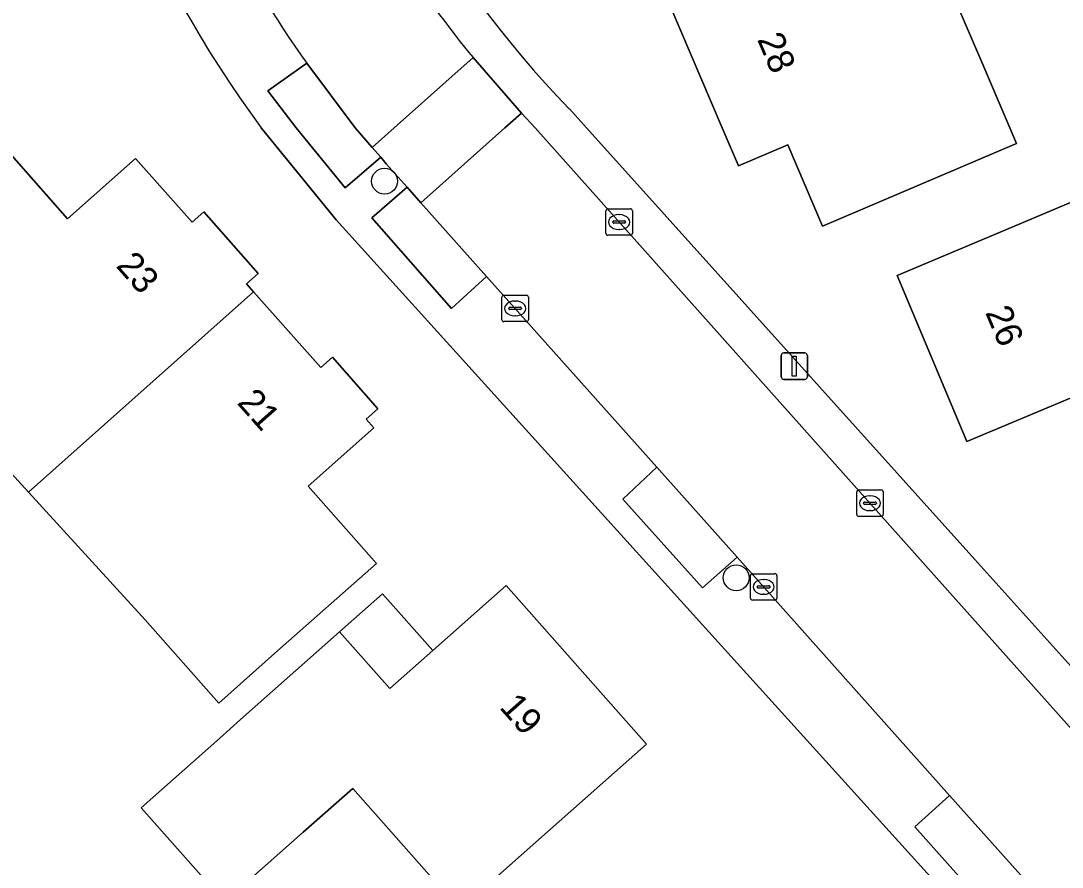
# Model space of a CAD drawing. Extents: x 158472 to 159562, y 388525 to 389606.
# Drawn here: x 158562.75 to 158602.12, y 388972.05 to 389004.05 of the extents above; entities that cross this region are included whole.
import ezdxf

# ---------------------------------------------------------------- set-up
doc = ezdxf.new("R2010")
doc.units = 0
for name, color, linetype in [('IMGEO_Boom', 7, 'Continuous'), ('IMGEO_Erf', 7, 'Continuous'), ('IMGEO_Kolk', 7, 'Continuous'), ('IMGEO_Lichtmast', 7, 'Continuous'), ('IMGEO_Pand', 7, 'Continuous'), ('IMGEO_Pand_nummerreeks', 7, 'Continuous'), ('IMGEO_Pand_overbouw', 7, 'Continuous'), ('IMGEO_Parkeervlak_open', 7, 'Continuous'), ('IMGEO_Rijbaan_lokaal_open', 7, 'Continuous'), ('IMGEO_Voetpad_open', 7, 'Continuous')]:
    doc.layers.add(name, color=color, linetype=linetype)

msp = doc.modelspace()

# ---------------------------------------------------------------- linework, layer by layer
at = {"layer": 'IMGEO_Boom'}
for centre in [(158576.499, 388997.986), (158589.795, 388982.99)]:
    msp.add_circle(centre, 0.489, dxfattribs=at)
at = {"layer": 'IMGEO_Erf'}
for points in [[(158602.302, 389007.333), (158597.826, 389005.427), (158599.08, 389002.483), (158600.39, 388999.407), (158593.063, 388996.286), (158591.753, 388999.362), (158589.877, 388998.563), (158589.266, 389000), (158587.286, 389004.646), (158590.327, 389005.942), (158588.597, 389010.003), (158593.198, 389011.963), (158599.235, 389014.534)], [(158570.23, 388978.252), (158567.451, 388981.394), (158563.036, 388986.227), (158560.673, 388988.814), (158560.23, 388988.409), (158553.333, 388986.547), (158550.683, 388989.543), (158558.185, 388996.179), (158561.93, 388999.491), (158564.515, 388996.568), (158567.089, 388998.844), (158569.222, 388996.432), (158569.665, 388996.824), (158571.726, 388994.495), (158571.282, 388994.102), (158571.547, 388993.803), (158574.084, 388990.935), (158574.526, 388991.326), (158576.249, 388989.379), (158575.806, 388988.987), (158576.098, 388988.658), (158573.613, 388986.459), (158576.201, 388983.533), (158572.456, 388980.221)], [(158606.765, 388994.404), (158608.141, 388994.982), (158609.038, 388992.848), (158610.51, 388989.345), (158608.463, 388988.485), (158603.853, 388986.547), (158602.481, 388989.812), (158598.518, 388988.146), (158595.878, 388994.425), (158600.488, 388996.363), (158605.122, 388998.311)], [(158579.346, 388970.448), (158575.294, 388975.023), (158573.422, 388973.365), (158570.449, 388970.732), (158567.294, 388974.295), (158570.267, 388976.928), (158571.057, 388977.628), (158574.8, 388980.942), (158576.426, 388982.381), (158578.325, 388980.237), (158581.102, 388982.696), (158586.409, 388976.703), (158582.666, 388973.389)], [(158574.8, 388980.942), (158576.7, 388978.797), (158578.325, 388980.237), (158576.426, 388982.381)]]:
    msp.add_lwpolyline(points, close=True, dxfattribs=at)
for points in [[(158583.486, 389000.717), (158584.132, 389000), (158598.813, 388983.685), (158608.009, 388973.467)], [(158631.972, 388946.242), (158635.311, 388942.532), (158643.817, 388950.009), (158644.553, 388955.191), (158638.495, 388969.468), (158636.325, 388970.661), (158633.535, 388969.353), (158634.702, 388966.578), (158636.899, 388967.502), (158642.704, 388953.698), (158640.483, 388952.764), (158640.89, 388951.797), (158637.438, 388950.345), (158637.031, 388951.312), (158630.51, 388948.57), (158623.539, 388965.148), (158608.557, 388958.887), (158601.535, 388966.825), (158598.936, 388969.698), (158591.991, 388977.375), (158574.672, 388996.519), (158571.833, 389000)]]:
    msp.add_lwpolyline(points, dxfattribs=at)
for centre, radius, start, end in [((158607.781, 389026.445), 44.627, 187.8492, 216.3397), ((158612.509, 389028.748), 40.35, 193.9452, 224.0034)]:
    msp.add_arc(centre, radius, start, end, dxfattribs=at)
at = {"layer": 'IMGEO_Kolk'}
for p, q in [((158584.869, 388996.014), (158584.869, 388996.866)), ((158584.944, 388996.94), (158585.796, 388996.94)), ((158585.357, 388996.72), (158585.382, 388996.72)), ((158585.87, 388996.866), (158585.87, 388996.014)), ((158585.128, 388996.434), (158585.128, 388996.446)), ((158585.566, 388996.397), (158585.168, 388996.397)), ((158585.171, 388996.483), (158585.569, 388996.483)), ((158585.612, 388996.446), (158585.612, 388996.434)), ((158585.796, 388995.94), (158584.944, 388995.94)), ((158585.38, 388996.16), (158585.355, 388996.16)), ((158580.939, 388992.748), (158580.939, 388993.6)), ((158581.014, 388993.674), (158581.866, 388993.674)), ((158581.94, 388993.6), (158581.94, 388992.748)), ((158581.198, 388993.168), (158581.198, 388993.18)), ((158581.636, 388993.131), (158581.238, 388993.131)), ((158581.241, 388993.217), (158581.639, 388993.217)), ((158581.427, 388993.454), (158581.452, 388993.454)), ((158581.682, 388993.18), (158581.682, 388993.168)), ((158581.45, 388992.894), (158581.425, 388992.894)), ((158581.866, 388992.674), (158581.014, 388992.674)), ((158594.353, 388985.383), (158594.353, 388986.235)), ((158594.428, 388986.309), (158595.28, 388986.309)), ((158594.841, 388986.089), (158594.866, 388986.089)), ((158595.354, 388986.235), (158595.354, 388985.383)), ((158594.612, 388985.803), (158594.612, 388985.815)), ((158595.05, 388985.766), (158594.652, 388985.766)), ((158594.655, 388985.852), (158595.053, 388985.852)), ((158595.096, 388985.815), (158595.096, 388985.803)), ((158595.28, 388985.309), (158594.428, 388985.309)), ((158594.864, 388985.529), (158594.839, 388985.529)), ((158590.333, 388982.219), (158590.333, 388983.071)), ((158590.408, 388983.145), (158591.26, 388983.145)), ((158590.821, 388982.925), (158590.846, 388982.925)), ((158591.334, 388983.071), (158591.334, 388982.219)), ((158590.592, 388982.639), (158590.592, 388982.651)), ((158591.03, 388982.602), (158590.632, 388982.602)), ((158590.635, 388982.688), (158591.033, 388982.688)), ((158591.076, 388982.651), (158591.076, 388982.639)), ((158591.26, 388982.145), (158590.408, 388982.145)), ((158590.844, 388982.365), (158590.819, 388982.365))]:
    msp.add_line(p, q, dxfattribs=at)
for points in [[(158584.869, 388996.014), (158584.869, 388996.866)], [(158584.944, 388996.94), (158585.796, 388996.94)], [(158585.87, 388996.866), (158585.87, 388996.014)], [(158585.796, 388995.94), (158584.944, 388995.94)], [(158580.939, 388992.748), (158580.939, 388993.6)], [(158581.014, 388993.674), (158581.866, 388993.674)], [(158581.94, 388993.6), (158581.94, 388992.748)], [(158581.866, 388992.674), (158581.014, 388992.674)], [(158594.353, 388985.383), (158594.353, 388986.235)], [(158594.428, 388986.309), (158595.28, 388986.309)], [(158595.354, 388986.235), (158595.354, 388985.383)], [(158595.28, 388985.309), (158594.428, 388985.309)], [(158590.333, 388982.219), (158590.333, 388983.071)], [(158590.408, 388983.145), (158591.26, 388983.145)], [(158591.334, 388983.071), (158591.334, 388982.219)], [(158591.26, 388982.145), (158590.408, 388982.145)]]:
    msp.add_lwpolyline(points, dxfattribs=at)
for centre, radius, start, end in [((158584.946, 388996.864), 0.0765, 91.552, 178.448), ((158584.946, 388996.864), 0.0765, 91.552, 178.448), ((158585.794, 388996.864), 0.0765, 1.552, 88.448), ((158585.794, 388996.864), 0.0765, 1.552, 88.448), ((158585.168, 388996.443), 0.0403, 85.8775, 175.7526), ((158585.165, 388996.433), 0.0366, 178.938, 274.7102), ((158585.569, 388996.44), 0.043, 264.8664, 352.4533), ((158585.573, 388996.445), 0.0386, 1.7309, 96.639), ((158584.946, 388996.016), 0.0765, 181.552, 268.448), ((158584.946, 388996.016), 0.0765, 181.552, 268.448), ((158585.794, 388996.016), 0.0765, 271.552, 358.448), ((158585.794, 388996.016), 0.0765, 271.552, 358.448), ((158581.016, 388993.598), 0.0765, 91.552, 178.448), ((158581.016, 388993.598), 0.0765, 91.552, 178.448), ((158581.864, 388993.598), 0.0765, 1.552, 88.448), ((158581.864, 388993.598), 0.0765, 1.552, 88.448), ((158581.238, 388993.177), 0.0403, 85.8775, 175.7526), ((158581.235, 388993.167), 0.0366, 178.938, 274.7102), ((158581.639, 388993.174), 0.043, 264.8664, 352.4533), ((158581.643, 388993.179), 0.0386, 1.7309, 96.639), ((158581.016, 388992.75), 0.0765, 181.552, 268.448), ((158581.016, 388992.75), 0.0765, 181.552, 268.448), ((158581.864, 388992.75), 0.0765, 271.552, 358.448), ((158581.864, 388992.75), 0.0765, 271.552, 358.448), ((158594.43, 388986.233), 0.0765, 91.552, 178.448), ((158594.43, 388986.233), 0.0765, 91.552, 178.448), ((158595.278, 388986.233), 0.0765, 1.552, 88.448), ((158595.278, 388986.233), 0.0765, 1.552, 88.448), ((158594.652, 388985.812), 0.0403, 85.8775, 175.7526), ((158594.649, 388985.802), 0.0366, 178.938, 274.7102), ((158595.053, 388985.809), 0.043, 264.8664, 352.4533), ((158595.057, 388985.814), 0.0386, 1.7309, 96.639), ((158594.43, 388985.385), 0.0765, 181.552, 268.448), ((158594.43, 388985.385), 0.0765, 181.552, 268.448), ((158595.278, 388985.385), 0.0765, 271.552, 358.448), ((158595.278, 388985.385), 0.0765, 271.552, 358.448), ((158590.41, 388983.069), 0.0765, 91.552, 178.448), ((158590.41, 388983.069), 0.0765, 91.552, 178.448), ((158591.258, 388983.069), 0.0765, 1.552, 88.448), ((158591.258, 388983.069), 0.0765, 1.552, 88.448), ((158590.632, 388982.648), 0.0403, 85.8775, 175.7526), ((158590.629, 388982.638), 0.0366, 178.938, 274.7102), ((158591.033, 388982.645), 0.043, 264.8664, 352.4533), ((158591.037, 388982.65), 0.0386, 1.7309, 96.639), ((158590.41, 388982.221), 0.0765, 181.552, 268.448), ((158590.41, 388982.221), 0.0765, 181.552, 268.448), ((158591.258, 388982.221), 0.0765, 271.552, 358.448), ((158591.258, 388982.221), 0.0765, 271.552, 358.448)]:
    msp.add_arc(centre, radius, start, end, dxfattribs=at)
for centre, major_axis, ratio, start_param, end_param in [((158585.356, 388996.44), (-0.387, 0.002), 0.722429, 4.712389, 7.853982), ((158585.381, 388996.44), (-0.39, 0.002), 0.717154, 1.570796, 4.712389), ((158581.426, 388993.174), (-0.387, 0.002), 0.722429, 4.712389, 7.853982), ((158581.451, 388993.174), (-0.39, 0.002), 0.717154, 1.570796, 4.712389), ((158594.84, 388985.809), (-0.387, 0.002), 0.722429, 4.712389, 7.853982), ((158594.865, 388985.809), (-0.39, 0.002), 0.717154, 1.570796, 4.712389), ((158590.82, 388982.645), (-0.387, 0.002), 0.722429, 4.712389, 7.853982), ((158590.845, 388982.645), (-0.39, 0.002), 0.717154, 1.570796, 4.712389)]:
    msp.add_ellipse(centre, major_axis=major_axis, ratio=ratio, start_param=start_param, end_param=end_param, dxfattribs=at)
at = {"layer": 'IMGEO_Lichtmast'}
for p, q in [((158591.496, 388990.591), (158591.496, 388991.391)), ((158591.496, 388991.391), (158591.496, 388990.591)), ((158591.596, 388991.491), (158592.386, 388991.491)), ((158592.386, 388991.491), (158591.596, 388991.491)), ((158592.486, 388991.391), (158592.486, 388990.591)), ((158592.486, 388990.591), (158592.486, 388991.391)), ((158592.386, 388990.491), (158591.596, 388990.491)), ((158591.596, 388990.491), (158592.386, 388990.491))]:
    msp.add_line(p, q, dxfattribs=at)
msp.add_lwpolyline([(158591.916, 388991.366), (158592.066, 388991.366), (158592.066, 388990.616), (158591.916, 388990.616), (158591.916, 388991.366)], dxfattribs=at)
for centre, start, end in [((158591.596, 388991.391), 90, 180), ((158591.596, 388991.391), 90, 180), ((158592.386, 388991.391), 0, 90), ((158592.386, 388991.391), 360, 90), ((158591.596, 388990.591), 180, 270), ((158591.596, 388990.591), 180, 270), ((158592.386, 388990.591), 270, 0), ((158592.386, 388990.591), 270, 0)]:
    msp.add_arc(centre, 0.1, start, end, dxfattribs=at)
at = {"layer": 'IMGEO_Pand'}
for points in [[(158589.877, 388998.563), (158591.753, 388999.362), (158593.063, 388996.286), (158600.39, 388999.407), (158599.08, 389002.483), (158597.826, 389005.427), (158602.302, 389007.333), (158599.235, 389014.534), (158593.198, 389011.963), (158588.597, 389010.003), (158590.327, 389005.942), (158587.286, 389004.646), (158589.266, 389000)], [(158571.547, 388993.803), (158571.282, 388994.102), (158571.726, 388994.495), (158569.665, 388996.824), (158569.222, 388996.432), (158567.089, 388998.844), (158564.515, 388996.568), (158561.93, 388999.491), (158558.185, 388996.179), (158550.683, 388989.543), (158553.333, 388986.547), (158560.23, 388988.409), (158560.673, 388988.814), (158563.036, 388986.227)], [(158605.122, 388998.311), (158600.488, 388996.363), (158595.878, 388994.425), (158598.518, 388988.146), (158602.481, 388989.812), (158603.853, 388986.547), (158608.463, 388988.485), (158610.51, 388989.345), (158609.038, 388992.848), (158608.141, 388994.982), (158606.765, 388994.404)], [(158571.547, 388993.803), (158563.036, 388986.227), (158567.451, 388981.394), (158570.23, 388978.252), (158572.456, 388980.221), (158576.201, 388983.533), (158573.613, 388986.459), (158576.098, 388988.658), (158575.806, 388988.987), (158576.249, 388989.379), (158574.526, 388991.326), (158574.084, 388990.935)], [(158570.267, 388976.928), (158567.294, 388974.295), (158570.449, 388970.732), (158573.422, 388973.365), (158575.294, 388975.023), (158579.346, 388970.448), (158582.666, 388973.389), (158586.409, 388976.703), (158581.102, 388982.696), (158578.325, 388980.237), (158576.7, 388978.797), (158574.8, 388980.942), (158571.057, 388977.628)]]:
    msp.add_lwpolyline(points, close=True, dxfattribs=at)
at = {"layer": 'IMGEO_Pand_overbouw'}
msp.add_lwpolyline([(158578.325, 388980.237), (158576.426, 388982.381), (158574.8, 388980.942), (158576.7, 388978.797)], close=True, dxfattribs=at)
at = {"layer": 'IMGEO_Parkeervlak_open'}
for points in [[(158576.361, 388998.896), (158576.03, 388999.253), (158575.389, 389000), (158573.558, 389002.444), (158572.081, 389001.396), (158573.154, 389000), (158575.007, 388997.738)], [(158577.349, 388997.756), (158576.013, 388996.599), (158579.036, 388993.176), (158580.36, 388994.381), (158577.871, 388997.171)], [(158586.79, 388987.175), (158585.506, 388985.968), (158588.521, 388982.609), (158589.832, 388983.765)], [(158600.876, 388971.386), (158597.864, 388974.762), (158596.547, 388973.568), (158599.538, 388970.215)]]:
    msp.add_lwpolyline(points, close=True, dxfattribs=at)
at = {"layer": 'IMGEO_Rijbaan_lokaal_open'}
for points in [[(158573.558, 389002.444), (158575.389, 389000), (158576.03, 388999.253), (158576.867, 389000), (158579.846, 389002.657)], [(158579.846, 389002.657), (158581.673, 389000.563), (158582.196, 389000), (158597.682, 388982.639), (158607.01, 388972.182)], [(158608.009, 388973.467), (158598.813, 388983.685), (158584.132, 389000), (158583.486, 389000.717)], [(158597.682, 388982.639), (158582.196, 389000), (158581.673, 389000.563), (158581.042, 389000), (158577.871, 388997.171), (158580.36, 388994.381), (158586.79, 388987.175), (158589.832, 388983.765), (158593.931, 388979.17), (158597.864, 388974.762), (158600.876, 388971.386), (158603.002, 388969.004)], [(158607.01, 388972.182), (158597.682, 388982.639)]]:
    msp.add_lwpolyline(points, dxfattribs=at)
msp.add_lwpolyline([(158581.673, 389000.563), (158579.846, 389002.657), (158576.867, 389000), (158576.03, 388999.253), (158576.361, 388998.896), (158576.564, 388998.636), (158577.349, 388997.756), (158577.871, 388997.171), (158581.042, 389000)], close=True, dxfattribs=at)
for centre, radius, start, end in [((158612.509, 389028.748), 40.35, 193.9452, 224.0034), ((158614.722, 389031.136), 45.027, 208.7652, 219.2339), ((158614.722, 389031.136), 45.027, 208.7652, 219.2339), ((158603.848, 389024.055), 37.209, 205.7679, 215.5063)]:
    msp.add_arc(centre, radius, start, end, dxfattribs=at)
at = {"layer": 'IMGEO_Voetpad_open'}
for points in [[(158593.931, 388979.17), (158589.832, 388983.765), (158588.521, 388982.609), (158585.506, 388985.968), (158586.79, 388987.175), (158580.36, 388994.381), (158579.036, 388993.176), (158576.013, 388996.599), (158577.349, 388997.756), (158576.564, 388998.636), (158576.361, 388998.896), (158575.007, 388997.738), (158573.154, 389000), (158572.081, 389001.396), (158573.558, 389002.444)], [(158571.833, 389000), (158574.672, 388996.519), (158591.991, 388977.375), (158598.936, 388969.698), (158599.538, 388970.215), (158596.547, 388973.568), (158597.864, 388974.762), (158593.931, 388979.17)]]:
    msp.add_lwpolyline(points, dxfattribs=at)
for centre, radius, start, end in [((158607.781, 389026.445), 44.627, 187.8492, 216.3397), ((158603.848, 389024.055), 37.209, 205.7679, 215.5063)]:
    msp.add_arc(centre, radius, start, end, dxfattribs=at)

# ---------------------------------------------------------------- texts
at = {"layer": 'IMGEO_Pand_nummerreeks'}
for s, rotation, p in [('28', 293.0728, (158590.577, 389003.349)), ('23', 311.4879, (158566.314, 388994.769)), ('26', 292.8035, (158599.2, 388993.023)), ('21', 311.4943, (158570.892, 388989.592)), ('19', 311.526, (158580.812, 388978.076))]:
    msp.add_text(s, height=1, rotation=rotation, dxfattribs=at).set_placement(p)

doc.saveas('drawing.dxf')
